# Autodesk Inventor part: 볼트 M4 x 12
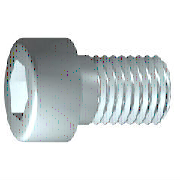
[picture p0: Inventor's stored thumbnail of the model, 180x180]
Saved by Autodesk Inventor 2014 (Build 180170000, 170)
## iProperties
IsCustomPart: 0
Created: 2012-02
Part Number: 볼트 M4 x 12
Material: 강철, 연강
Description: 6각 소켓 머리 캡 나사
Document SubType Name: Modeling
Standard: ISO 4762
Designer: mduedu
Standard Revision: Fourth edition 2004-03-01
Standards Organization: ISO
Language: ko-KR
Size Designation: M4 x 12
Categories: <MemberInstance><Categories><Category DisplayName="조임쇠" InternalName="e4da775c-781d-43d5-af7c-5136215cf5a6" Mnemonic="FSTN"><Category DisplayName="볼트" InternalN
Density: 7.75 g/cm^3
Appearance: 강철
Author: mduedu
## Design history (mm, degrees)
sketch "스케치1"
  geometry: L1 (-1, 0)-(12, 0); L2 (12, 0)-(12, 2); L3 (12, 2)-(1.75, 2); L4 (1.75, 2)-(1.32, 2); L5 (1.32, 2)-(0, 2); L6 (0, 2)-(0, 3.5); L7 (0, 3.5)-(-4, 3.5); L8 (-4, 3.5)-(-4, 1.732); L9 (-4, 1.732)-(-2, 1.732); L10 (-2, 1.732)-(-1, 0); L11 (-7.2, 0)-(15.2, 0) reference; L12 (0, -0.7)-(0, 4.2) reference; L13 (1.75, 2)-(0, 2)
  constraints: 22 end point, 6 parallel, 2 collinear, 2 perpendicular, 1 horizontal, 1 point on line
  dimensions: "d1" = 10.25 distance from line of L3.end L2 (= GEL); "d2" = 0.42952 distance of L4.end L3.end (computed from GAL); "d3" = 4 distance between parallel lines of L8 L6 (= KOH); "d4" = 2 distance of L8.end L9.end (= INTI); "d5" = 60 deg angle of L10 L1; "d6" = 4 diameter of L3 L1 (= GD); "d7" = 4 diameter of L5 L1 (= BDM); "d8" = 3.4641 diameter of L9 L1 (= 1.1547 x SW); "d9" = 7 diameter of L7 L1 (= KOD); "d26" = 12 distance between parallel lines of L12 L2 (= NLG)
revolve "본체" sketch "스케치1" stored, may be unused: angle "d10" = 90 deg
sketch "스케치2"
  geometry: L1 (0, -4.9)-(0, 4.9) reference; L2 (-4.9, 0)-(4.9, 0) reference; L3 (1.732, 0)-(0.866, -1.5); L4 (0.866, -1.5)-(-0.866, -1.5); L5 (-0.866, -1.5)-(-1.732, 0); L6 (-1.732, 0)-(-0.866, 1.5); L7 (-0.866, 1.5)-(0.866, 1.5); L8 (0.866, 1.5)-(1.732, 0); 2 further points
  constraints: 12 end point, 1 coincident, 1 horizontal alignment, 1 point on line, 12 other
extrude "슬롯" join sketch "스케치2" stored distance "d11" = 10; taper "d12" = 0 deg
workplane "Work Plane1"
fillet "Fillet2" dims "d30" = 0.1 (= R)
body "Solid1"
fillet "모깎기1" dims "d17" = 0.4 (= RR)
feature "스레드" dims "d13" = 10.25 (= GEL), "d14" = 0
chamfer "모따기1" distance "d15" = 0.42941 (= -0.5 x SPD + 0.5 x GD); stored, may be unused: second distance "d16" = 0.42941 (= GUL), angle "d27" = 45 deg
other parameters: "GD" = 4 [user parameter; used in 2 equation terms], "NLG" = 12 [user parameter; used in 1 equation term], "GEL" = 10.25 [user parameter; used in 2 equation terms], "KOD" = 7 [user parameter; used in 1 equation term], "KOH" = 4 [user parameter; used in 1 equation term], "INTI" = 2 [user parameter; used in 1 equation term], "GAL" = 0.42941 (= 0.61345 x PTC) [user parameter; used in 1 equation term], "GUL" = 0.42941 (= 0.61345 x PTC) [user parameter; used in 1 equation term], "BDM" = 4 (= NND) [user parameter; used in 1 equation term], "SW" = 3 [user parameter; used in 2 equation terms], "RR" = 0.4 [user parameter; used in 1 equation term], "SPD" = 3.14117 (= NND - 1.2269 x PTC) [user parameter; used in 1 equation term], "d19" = 0, "d28" = 0, "d29" = 0, "R" = 0.1 [user parameter; used in 1 equation term], "TOA" = 30 deg [user parameter], "GD1" = 3.14117 (= THREADDIA - 1.2269 x PTC) [user parameter], "THREADDIA" = 4 [user parameter; used in 1 equation term], "FAWI" = 45 deg [user parameter], "TPU" = 14.28571 (computed from PTC) [user parameter], "PTC" = 0.7 [user parameter; used in 5 equation terms], "NND" = 4 [user parameter; used in 2 equation terms], "E0" = 3.465 (= 1.155 x SW) [user parameter]
